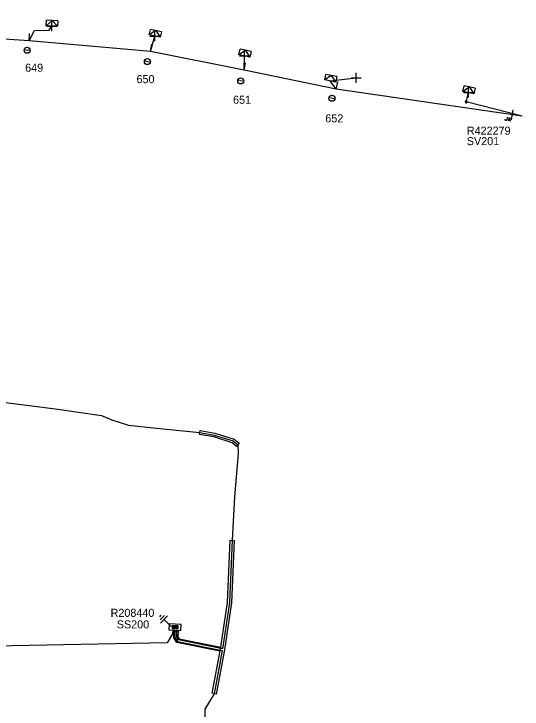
# Model space of a CAD drawing. Extents: x -540466 to -537383, y -1184038 to -1179972.
# Drawn here: x -538655.3 to -538592.1, y -1180221.7 to -1180135.3 of the extents above; entities that cross this region are included whole.
import ezdxf

# ---------------------------------------------------------------- set-up
doc = ezdxf.new("R2010")
doc.units = 0
for name, color, linetype in [('Vrstva 1', 7, 'Continuous'), ('Vrstva 10', 7, 'Continuous'), ('Vrstva 13', 7, 'Continuous'), ('Vrstva 14', 7, 'Continuous'), ('Vrstva 15', 7, 'Continuous'), ('Vrstva 18', 7, 'Continuous'), ('Vrstva 2', 7, 'Continuous'), ('Vrstva 20', 7, 'Continuous'), ('Vrstva 28', 7, 'Continuous'), ('Vrstva 29', 7, 'Continuous'), ('Vrstva 30', 7, 'Continuous'), ('Vrstva 31', 7, 'Continuous'), ('Vrstva 34', 7, 'Continuous'), ('Vrstva 36', 7, 'Continuous'), ('Vrstva 5', 7, 'Continuous'), ('Vrstva 52', 7, 'Continuous'), ('Vrstva 54', 7, 'Continuous'), ('Vrstva 59', 7, 'Continuous'), ('Vrstva 8', 7, 'Continuous'), ('Vrstva 9', 7, 'Continuous')]:
    doc.layers.add(name, color=color, linetype=linetype)

# ---------------------------------------------------------------- blocks, each defined once
blk = doc.blocks.new('NN840')
at = {"layer": 'Vrstva 15'}
for points in [[(0.003, 0.619), (0.003, -0.631)], [(-0.745, -0.71), (-0.745, -0.66)], [(-0.73, -0.764), (-0.745, -0.71)], [(-0.657, -0.798), (-0.73, -0.764)], [(-0.627, -0.798), (-0.657, -0.798)], [(-0.558, -0.764), (-0.627, -0.798)], [(-0.538, -0.71), (-0.558, -0.764)], [(-0.538, -0.385), (-0.538, -0.71)], [(-0.332, -0.385), (-0.332, -0.798)], [(-0.332, -0.641), (-0.125, -0.385)], [(-0.263, -0.557), (-0.091, -0.798)]]:
    blk.add_lwpolyline(points, dxfattribs=at)
blk = doc.blocks.new('NN770')
at = {"layer": 'Vrstva 10'}
for p, q in [((0.002, 0.187), (0.002, 0.263)), ((0.002, -0.276), (0.002, 0.111))]:
    blk.add_line(p, q, dxfattribs=at)
blk.add_circle((0, -0.008), 0.375, dxfattribs=at)
blk = doc.blocks.new('NN800')
at = {"layer": 'Vrstva 1'}
for points in [[(-0.442, 0.442), (0.442, -0.442)], [(-0.442, -0.442), (0.442, 0.442)]]:
    blk.add_lwpolyline(points, dxfattribs=at)
blk = doc.blocks.new('NN620')
at = {"layer": 'Vrstva 8'}
for points in [[(0.752, 0.004), (-0.748, 0.004)], [(-0.748, 0.004), (-0.748, -0.746)], [(0.752, -0.746), (0.752, 0.004)], [(-0.748, -0.746), (0.752, -0.746)], [(0.368, -0.18), (-0.376, -0.18)], [(-0.376, -0.18), (-0.376, -0.558)], [(-0.376, -0.558), (0.368, -0.558)], [(0.321, -0.227), (-0.329, -0.227)], [(-0.329, -0.227), (-0.329, -0.51)], [(-0.329, -0.51), (0.321, -0.51)], [(0.274, -0.274), (-0.281, -0.274)], [(-0.281, -0.274), (-0.281, -0.463)], [(-0.281, -0.463), (0.274, -0.463)], [(0.227, -0.321), (-0.234, -0.321)], [(-0.234, -0.321), (-0.234, -0.416)], [(-0.234, -0.416), (0.227, -0.416)], [(-0.193, -0.369), (0.185, -0.369)], [(0.227, -0.416), (0.227, -0.321)], [(0.274, -0.463), (0.274, -0.274)], [(0.321, -0.51), (0.321, -0.227)], [(0.368, -0.558), (0.368, -0.18)]]:
    blk.add_lwpolyline(points, dxfattribs=at)
blk = doc.blocks.new('NN630')
at = {"layer": 'Vrstva 9'}
for points in [[(-0.003, -0.7), (-0.703, 0)], [(-0.703, -0.7), (-0.703, 0), (0.697, 0), (0.697, -0.7)], [(-0.703, -0.7), (0.697, -0.7)], [(-0.003, -0.7), (0.697, 0)]]:
    blk.add_lwpolyline(points, dxfattribs=at)
blk = doc.blocks.new('NN810')
at = {"layer": 'Vrstva 14'}
for points in [[(0.004, -0.64), (0.004, -1.89)], [(0.629, -1.89), (-0.621, -1.89)], [(0.388, -2.2), (-0.399, -2.2)], [(0.004, -2.515), (-0.124, -2.515)], [(0.137, -2.515), (0.004, -2.515)]]:
    blk.add_lwpolyline(points, dxfattribs=at)
blk = doc.blocks.new('NN500')
at = {"layer": 'Vrstva 2'}
for points in [[(0, -0.24), (0.02, -0.23), (0.05, -0.23), (0.07, -0.22), (0.09, -0.22), (0.12, -0.2), (0.14, -0.19), (0.16, -0.18), (0.17, -0.16), (0.19, -0.14), (0.2, -0.12), (0.21, -0.1), (0.22, -0.07), (0.23, -0.05), (0.23, -0.02), (0.23, 0), (0.23, 0.02), (0.23, 0.05), (0.22, 0.07), (0.21, 0.1), (0.2, 0.12), (0.19, 0.14), (0.17, 0.16), (0.16, 0.17), (0.14, 0.19), (0.12, 0.2), (0.09, 0.21), (0.07, 0.22), (0.05, 0.23), (0.02, 0.23), (0, 0.23), (-0.03, 0.23), (-0.05, 0.23), (-0.07, 0.22), (-0.1, 0.21), (-0.12, 0.2), (-0.14, 0.19), (-0.16, 0.17), (-0.18, 0.16), (-0.19, 0.14), (-0.2, 0.12), (-0.22, 0.1), (-0.22, 0.07), (-0.23, 0.05), (-0.23, 0.02), (-0.24, 0), (-0.23, -0.02), (-0.23, -0.05), (-0.22, -0.07), (-0.22, -0.1), (-0.2, -0.12), (-0.19, -0.14), (-0.18, -0.16), (-0.16, -0.18), (-0.14, -0.19), (-0.12, -0.2), (-0.1, -0.22), (-0.07, -0.22), (-0.05, -0.23), (-0.03, -0.23), (0, -0.24)], [(0, -0.24), (0.02, -0.23), (0.05, -0.23), (0.07, -0.22), (0.09, -0.22), (0.12, -0.2), (0.14, -0.19), (0.16, -0.18), (0.17, -0.16), (0.19, -0.14), (0.2, -0.12), (0.21, -0.1), (0.22, -0.07), (0.23, -0.05), (0.23, -0.02), (0.23, 0), (0.23, 0.02), (0.23, 0.05), (0.22, 0.07), (0.21, 0.1), (0.2, 0.12), (0.19, 0.14), (0.17, 0.16), (0.16, 0.17), (0.14, 0.19), (0.12, 0.2), (0.09, 0.21), (0.07, 0.22), (0.05, 0.23), (0.02, 0.23), (0, 0.23), (-0.03, 0.23), (-0.05, 0.23), (-0.07, 0.22), (-0.1, 0.21), (-0.12, 0.2), (-0.14, 0.19), (-0.16, 0.17), (-0.18, 0.16), (-0.19, 0.14), (-0.2, 0.12), (-0.22, 0.1), (-0.22, 0.07), (-0.23, 0.05), (-0.23, 0.02), (-0.24, 0), (-0.23, -0.02), (-0.23, -0.05), (-0.22, -0.07), (-0.22, -0.1), (-0.2, -0.12), (-0.19, -0.14), (-0.18, -0.16), (-0.16, -0.18), (-0.14, -0.19), (-0.12, -0.2), (-0.1, -0.22), (-0.07, -0.22), (-0.05, -0.23), (-0.03, -0.23), (0, -0.24)], [(0, -0.21), (0.02, -0.2), (0.04, -0.2), (0.06, -0.2), (0.08, -0.19), (0.1, -0.18), (0.12, -0.17), (0.14, -0.15), (0.15, -0.14), (0.16, -0.12), (0.18, -0.1), (0.19, -0.08), (0.19, -0.06), (0.2, -0.04), (0.2, -0.02), (0.2, 0), (0.2, 0.02), (0.2, 0.04), (0.19, 0.06), (0.19, 0.08), (0.18, 0.1), (0.16, 0.12), (0.15, 0.14), (0.14, 0.15), (0.12, 0.17), (0.1, 0.18), (0.08, 0.19), (0.06, 0.19), (0.04, 0.2), (0.02, 0.2), (0, 0.2), (-0.02, 0.2), (-0.04, 0.2), (-0.06, 0.19), (-0.08, 0.19), (-0.1, 0.18), (-0.12, 0.17), (-0.14, 0.15), (-0.15, 0.14), (-0.17, 0.12), (-0.18, 0.1), (-0.19, 0.08), (-0.2, 0.06), (-0.2, 0.04), (-0.21, 0.02), (-0.21, 0), (-0.21, -0.02), (-0.2, -0.04), (-0.2, -0.06), (-0.19, -0.08), (-0.18, -0.1), (-0.17, -0.12), (-0.15, -0.14), (-0.14, -0.15), (-0.12, -0.17), (-0.1, -0.18), (-0.08, -0.19), (-0.06, -0.2), (-0.04, -0.2), (-0.02, -0.2), (0, -0.21)], [(0, -0.18), (0.02, -0.18), (0.04, -0.17), (0.05, -0.17), (0.07, -0.16), (0.09, -0.15), (0.1, -0.14), (0.12, -0.13), (0.13, -0.12), (0.14, -0.1), (0.15, -0.09), (0.16, -0.07), (0.17, -0.05), (0.17, -0.04), (0.17, -0.02), (0.17, 0), (0.17, 0.02), (0.17, 0.04), (0.17, 0.05), (0.16, 0.07), (0.15, 0.09), (0.14, 0.1), (0.13, 0.12), (0.12, 0.13), (0.1, 0.14), (0.09, 0.15), (0.07, 0.16), (0.05, 0.17), (0.04, 0.17), (0.02, 0.17), (0, 0.18), (-0.02, 0.17), (-0.04, 0.17), (-0.06, 0.17), (-0.07, 0.16), (-0.09, 0.15), (-0.1, 0.14), (-0.12, 0.13), (-0.13, 0.12), (-0.14, 0.1), (-0.15, 0.09), (-0.16, 0.07), (-0.17, 0.05), (-0.17, 0.04), (-0.18, 0.02), (-0.18, 0), (-0.18, -0.02), (-0.17, -0.04), (-0.17, -0.05), (-0.16, -0.07), (-0.15, -0.09), (-0.14, -0.1), (-0.13, -0.12), (-0.12, -0.13), (-0.1, -0.14), (-0.09, -0.15), (-0.07, -0.16), (-0.06, -0.17), (-0.04, -0.17), (-0.02, -0.18), (0, -0.18)], [(0, -0.15), (0.01, -0.15), (0.03, -0.14), (0.04, -0.14), (0.06, -0.13), (0.07, -0.13), (0.08, -0.12), (0.1, -0.11), (0.11, -0.1), (0.12, -0.09), (0.13, -0.07), (0.13, -0.06), (0.14, -0.05), (0.14, -0.03), (0.14, -0.02), (0.14, 0), (0.14, 0.01), (0.14, 0.03), (0.14, 0.04), (0.13, 0.06), (0.13, 0.07), (0.12, 0.09), (0.11, 0.1), (0.1, 0.11), (0.08, 0.12), (0.07, 0.13), (0.06, 0.13), (0.04, 0.14), (0.03, 0.14), (0.01, 0.14), (0, 0.15), (-0.02, 0.14), (-0.03, 0.14), (-0.05, 0.14), (-0.06, 0.13), (-0.07, 0.13), (-0.09, 0.12), (-0.1, 0.11), (-0.11, 0.1), (-0.12, 0.09), (-0.13, 0.07), (-0.13, 0.06), (-0.14, 0.04), (-0.14, 0.03), (-0.15, 0.01), (-0.15, 0), (-0.15, -0.02), (-0.14, -0.03), (-0.14, -0.05), (-0.13, -0.06), (-0.13, -0.07), (-0.12, -0.09), (-0.11, -0.1), (-0.1, -0.11), (-0.09, -0.12), (-0.07, -0.13), (-0.06, -0.13), (-0.05, -0.14), (-0.03, -0.14), (-0.02, -0.15), (0, -0.15)], [(0, -0.12), (0.01, -0.12), (0.02, -0.11), (0.03, -0.11), (0.05, -0.11), (0.06, -0.1), (0.07, -0.09), (0.08, -0.09), (0.09, -0.08), (0.09, -0.07), (0.1, -0.06), (0.11, -0.05), (0.11, -0.04), (0.11, -0.02), (0.11, -0.01), (0.12, 0), (0.11, 0.01), (0.11, 0.02), (0.11, 0.04), (0.11, 0.05), (0.1, 0.06), (0.09, 0.07), (0.09, 0.08), (0.08, 0.09), (0.07, 0.09), (0.06, 0.1), (0.05, 0.11), (0.03, 0.11), (0.02, 0.11), (0.01, 0.12), (0, 0.12), (-0.01, 0.12), (-0.03, 0.11), (-0.04, 0.11), (-0.05, 0.11), (-0.06, 0.1), (-0.07, 0.09), (-0.08, 0.09), (-0.09, 0.08), (-0.1, 0.07), (-0.1, 0.06), (-0.11, 0.05), (-0.11, 0.04), (-0.12, 0.02), (-0.12, 0.01), (-0.12, 0), (-0.12, -0.01), (-0.12, -0.02), (-0.11, -0.04), (-0.11, -0.05), (-0.1, -0.06), (-0.1, -0.07), (-0.09, -0.08), (-0.08, -0.09), (-0.07, -0.09), (-0.06, -0.1), (-0.05, -0.11), (-0.04, -0.11), (-0.03, -0.11), (-0.01, -0.12), (0, -0.12)], [(0, -0.09), (0.01, -0.09), (0.02, -0.09), (0.03, -0.08), (0.03, -0.08), (0.04, -0.08), (0.05, -0.07), (0.06, -0.07), (0.06, -0.06), (0.07, -0.05), (0.07, -0.04), (0.08, -0.04), (0.08, -0.03), (0.08, -0.02), (0.09, -0.01), (0.09, 0), (0.09, 0.01), (0.08, 0.02), (0.08, 0.03), (0.08, 0.03), (0.07, 0.04), (0.07, 0.05), (0.06, 0.06), (0.06, 0.06), (0.05, 0.07), (0.04, 0.07), (0.03, 0.08), (0.03, 0.08), (0.02, 0.08), (0.01, 0.09), (0, 0.09), (-0.01, 0.09), (-0.02, 0.08), (-0.03, 0.08), (-0.04, 0.08), (-0.04, 0.07), (-0.05, 0.07), (-0.06, 0.06), (-0.07, 0.06), (-0.07, 0.05), (-0.08, 0.04), (-0.08, 0.03), (-0.08, 0.03), (-0.09, 0.02), (-0.09, 0.01), (-0.09, 0), (-0.09, -0.01), (-0.09, -0.02), (-0.08, -0.03), (-0.08, -0.04), (-0.08, -0.04), (-0.07, -0.05), (-0.07, -0.06), (-0.06, -0.07), (-0.05, -0.07), (-0.04, -0.08), (-0.04, -0.08), (-0.03, -0.08), (-0.02, -0.09), (-0.01, -0.09), (0, -0.09)], [(0, -0.06), (0, -0.06), (0.01, -0.06), (0.02, -0.05), (0.02, -0.05), (0.03, -0.05), (0.03, -0.05), (0.04, -0.04), (0.04, -0.04), (0.05, -0.03), (0.05, -0.03), (0.05, -0.02), (0.05, -0.02), (0.05, -0.01), (0.06, -0.01), (0.06, 0), (0.06, 0.01), (0.05, 0.01), (0.05, 0.02), (0.05, 0.02), (0.05, 0.03), (0.05, 0.03), (0.04, 0.04), (0.04, 0.04), (0.03, 0.05), (0.03, 0.05), (0.02, 0.05), (0.02, 0.05), (0.01, 0.06), (0, 0.06), (0, 0.06), (-0.01, 0.06), (-0.01, 0.06), (-0.02, 0.05), (-0.02, 0.05), (-0.03, 0.05), (-0.03, 0.05), (-0.04, 0.04), (-0.04, 0.04), (-0.05, 0.03), (-0.05, 0.03), (-0.05, 0.02), (-0.06, 0.02), (-0.06, 0.01), (-0.06, 0.01), (-0.06, 0), (-0.06, -0.01), (-0.06, -0.01), (-0.06, -0.02), (-0.05, -0.02), (-0.05, -0.03), (-0.05, -0.03), (-0.04, -0.04), (-0.04, -0.04), (-0.03, -0.05), (-0.03, -0.05), (-0.02, -0.05), (-0.02, -0.05), (-0.01, -0.06), (-0.01, -0.06), (0, -0.06)], [(0, -0.03), (0, -0.03), (0, -0.03), (0.01, -0.03), (0.01, -0.03), (0.01, -0.02), (0.02, -0.02), (0.02, -0.02), (0.02, -0.02), (0.02, -0.02), (0.02, -0.01), (0.02, -0.01), (0.03, -0.01), (0.03, -0.01), (0.03, 0), (0.03, 0), (0.03, 0), (0.03, 0.01), (0.03, 0.01), (0.02, 0.01), (0.02, 0.01), (0.02, 0.02), (0.02, 0.02), (0.02, 0.02), (0.02, 0.02), (0.01, 0.02), (0.01, 0.02), (0.01, 0.03), (0, 0.03), (0, 0.03), (0, 0.03), (0, 0.03), (-0.01, 0.03), (-0.01, 0.03), (-0.01, 0.02), (-0.02, 0.02), (-0.02, 0.02), (-0.02, 0.02), (-0.02, 0.02), (-0.02, 0.02), (-0.03, 0.01), (-0.03, 0.01), (-0.03, 0.01), (-0.03, 0.01), (-0.03, 0), (-0.03, 0), (-0.03, 0), (-0.03, -0.01), (-0.03, -0.01), (-0.03, -0.01), (-0.03, -0.01), (-0.02, -0.02), (-0.02, -0.02), (-0.02, -0.02), (-0.02, -0.02), (-0.02, -0.02), (-0.01, -0.03), (-0.01, -0.03), (-0.01, -0.03), (0, -0.03), (0, -0.03)], [(0.23, 0), (0.7, 0)]]:
    blk.add_lwpolyline(points, dxfattribs=at)
blk = doc.blocks.new('NN510')
at = {"layer": 'Vrstva 2'}
blk.add_lwpolyline([(0.001, 0.002), (0.001, 0.939)], dxfattribs=at)

msp = doc.modelspace()

# ---------------------------------------------------------------- linework, layer by layer
at = {"layer": 'Vrstva 1'}
msp.add_lwpolyline([(-538592.137, -1180148.014), (-538615.217, -1180144.633), (-538626.671, -1180142.279), (-538638.304, -1180139.964), (-538653.378, -1180138.65), (-538660.91, -1180138.14), (-538679.97, -1180135.99), (-538689.39, -1180135.29)], dxfattribs=at)
at = {"layer": 'Vrstva 20'}
for points in [[(-538632.125, -1180187.044), (-538630.31, -1180187.377), (-538627.908, -1180188.136), (-538627.291, -1180188.647), (-538627.609, -1180189.033), (-538628.152, -1180188.584), (-538630.43, -1180187.863), (-538632.215, -1180187.536)], [(-538628.39, -1180200.687), (-538627.89, -1180200.71), (-538628.241, -1180208.453), (-538629.113, -1180214.331), (-538630.134, -1180219.806), (-538630.626, -1180219.714), (-538629.607, -1180214.249), (-538628.74, -1180208.431)], [(-538629.561, -1180213.99), (-538629.66, -1180214.481), (-538635.024, -1180213.404), (-538635.384, -1180212.837), (-538635.34, -1180211.948), (-538634.84, -1180211.972), (-538634.876, -1180212.703), (-538634.716, -1180212.956)]]:
    msp.add_lwpolyline(points, close=True, dxfattribs=at)
at = {"layer": 'Vrstva 5'}
for points in [[(-538660.145, -1180184.979), (-538660.07, -1180184), (-538659.32, -1180183.34), (-538656.61, -1180183.53), (-538650.09, -1180184.38), (-538644.38, -1180185.19), (-538643.11, -1180185.75), (-538641.01, -1180186.4), (-538637.53, -1180186.77), (-538632.17, -1180187.29), (-538630.37, -1180187.62), (-538628.03, -1180188.36), (-538627.45, -1180188.84), (-538627.42, -1180189.93), (-538627.84, -1180195.3), (-538628.14, -1180200.7), (-538628.49, -1180208.43), (-538629.329, -1180214.169), (-538634.793, -1180213.068), (-538635.003, -1180212.736), (-538635.006, -1180212.042), (-538635.007, -1180211.842)], [(-538635.257, -1180211.861), (-538635.257, -1180212.804), (-538634.947, -1180213.292), (-538629.383, -1180214.413), (-538630.38, -1180219.76), (-538631.54, -1180221.67), (-538631.28, -1180234.07), (-538631.22, -1180239.48), (-538631.27, -1180243.73), (-538632.31, -1180244.827), (-538633.877, -1180244.865), (-538636.275, -1180244.978), (-538636.694, -1180244.998), (-538637.244, -1180245.355)]]:
    msp.add_lwpolyline(points, dxfattribs=at)
at = {"layer": 'Vrstva 52'}
msp.add_lwpolyline([(-538635.531, -1180211.829), (-538635.539, -1180212.328), (-538636.206, -1180213.432), (-538664.139, -1180213.965), (-538667.303, -1180218.579), (-538667.737, -1180218.65)], dxfattribs=at)
at = {"layer": 'Vrstva 54'}
for points in [[(-538638.304, -1180139.964), (-538637.76, -1180138.042)], [(-538626.671, -1180142.279), (-538626.629, -1180140.514)], [(-538592.137, -1180148.014), (-538599.08, -1180146.211), (-538598.808, -1180145.065)]]:
    msp.add_lwpolyline(points, dxfattribs=at)
at = {"layer": 'Vrstva 59'}
msp.add_lwpolyline([(-538615.971, -1180143.625), (-538612.736, -1180143.224)], dxfattribs=at)
at = {"layer": 'Vrstva 8'}
for points in [[(-538653.378, -1180138.65), (-538652.708, -1180137.355), (-538650.867, -1180137.316), (-538650.532, -1180136.806)], [(-538615.217, -1180144.633), (-538615.971, -1180143.625)]]:
    msp.add_lwpolyline(points, dxfattribs=at)

# ---------------------------------------------------------------- block references
at = {"layer": 'Vrstva 13'}
for p, rotation in [((-538653.378, -1180138.65), -4.6767416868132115), ((-538638.304, -1180139.964), -11.656594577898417), ((-538626.671, -1180142.279), -11.656594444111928), ((-538615.217, -1180144.633), -11.754347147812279)]:
    msp.add_blockref('NN510', p, dxfattribs=dict(at, rotation=rotation))
at = {"layer": 'Vrstva 13', "xscale": 0.5000000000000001, "yscale": 0.5, "rotation": 77.78599997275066}
msp.add_blockref('NN500', (-538599.08, -1180146.211), dxfattribs=at)
at = {"layer": 'Vrstva 15', "rotation": -134.632805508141}
msp.add_blockref('NN810', (-538635.257, -1180211.861), dxfattribs=at)
at = {"layer": 'Vrstva 18', "rotation": -8.334148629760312}
msp.add_blockref('NN840', (-538593.389, -1180147.831), dxfattribs=at)
at = {"layer": 'Vrstva 28', "rotation": 176.17636957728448}
msp.add_blockref('NN620', (-538635.257, -1180211.861), dxfattribs=at)
at = {"layer": 'Vrstva 31'}
for p, rotation in [((-538650.532, -1180136.806), 177.90065551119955), ((-538637.76, -1180138.042), 168.34340556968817), ((-538626.629, -1180140.514), 168.34340556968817), ((-538615.97, -1180143.625), 168.86536945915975), ((-538598.808, -1180145.065), 167.78617777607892)]:
    msp.add_blockref('NN630', p, dxfattribs=dict(at, rotation=rotation))
at = {"layer": 'Vrstva 34'}
for p, rotation in [((-538650.532, -1180136.806), 45), ((-538637.76, -1180138.042), 45), ((-538626.629, -1180140.514), 44.99999995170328), ((-538612.736, -1180143.224), 45.000000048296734), ((-538598.808, -1180145.065), 45.00000009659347)]:
    msp.add_blockref('NN800', p, dxfattribs=dict(at, rotation=rotation))
at = {"layer": 'Vrstva 36'}
for p, rotation in [((-538653.619, -1180139.807), 85.34806664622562), ((-538638.681, -1180141.22), 78.36636670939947), ((-538627.09, -1180143.613), 78.36636673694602), ((-538615.761, -1180145.771), 78.24666667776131)]:
    msp.add_blockref('NN770', p, dxfattribs=dict(at, rotation=rotation))

# ---------------------------------------------------------------- texts
at = {"layer": 'Vrstva 14'}
for s, p in [('649', (-538653.857, -1180142.477)), ('650', (-538640.022, -1180143.894)), ('651', (-538628.034, -1180146.456)), ('652', (-538616.575, -1180148.77))]:
    msp.add_text(s, height=1, dxfattribs=at).set_placement(p)
at = {"layer": 'Vrstva 29'}
for s, p in [('R422279', (-538599, -1180150.3)), ('R208440', (-538643.242, -1180210.213))]:
    msp.add_text(s, height=1, dxfattribs=at).set_placement(p)
at = {"layer": 'Vrstva 30'}
for s, p in [('SV201', (-538599, -1180151.6)), ('SS200', (-538642.475, -1180211.647))]:
    msp.add_text(s, height=1, dxfattribs=at).set_placement(p)

doc.saveas('drawing.dxf')
